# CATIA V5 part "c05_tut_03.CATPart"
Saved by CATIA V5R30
Part number: Part1
Bounding box of the stored display mesh (mm): x -75 to 75, y -150 to 150, z 39 to 189
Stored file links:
  D:\PROJECTS\CATIA V56R 2020\Resources\c05_catia_v5_6r2020_tut\c05_tut_03.CATPart
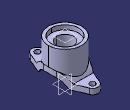
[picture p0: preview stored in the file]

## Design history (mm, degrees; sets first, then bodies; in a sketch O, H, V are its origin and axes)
Body1 (main body)
  Sketch1 on yz-plane, origin (0, 0, 0), H (0, 1, 0), V (0, 0, 1)
    arc A1 centre (0, 0) radius 105 from (83.2406, 64) to (-83.2406, 64) ccw
    arc A2 centre (0, 0) radius 80 from (69.8498, 39) to (-69.8498, 39) ccw
    line L1 (69.8498, 39) -> (150, 39)
    line L2 (150, 39) -> (150, 64)
    line L3 (150, 64) -> (83.2406, 64)
    point P5 (-83.2406, 64)
    line L4 (-83.2406, 64) -> (-150, 64)
    line L5 (-150, 64) -> (-150, 39)
    point P7 (-150, 39)
    line L6 (-150, 39) -> (-69.8498, 39)
    radius A1 = 105
    radius A2 = 80
    distance L3 L1 = 25
    distance H L1 = 39
    distance V L5 = 150
    horizontal: L1 H, L3 H, L4 H, L6 H
    vertical: L2 V, L5 V
    coincidence: P5 L3, P7 L1
    symmetry: L5 L2 V
  Pad1: profile Sketch1, direction (1, 0, 0), length 75, mirrored extent
  Sketch2 on xy-plane, origin (0, 0, 0), H (1, 0, 0), V (0, 1, 0)
    arc A1 centre (0, 0) radius 75 from (-68.7386, 30) to (-68.7386, -30) ccw
    arc A2 centre (0, 125) radius 25 from (22.9129, 135) to (-22.9129, 135) ccw
    point P1 (0, 125)
    point P2 (0, 150)
    arc A3 centre (0, -125) radius 25 from (-22.9129, -135) to (22.9129, -135) ccw
    point P3 (0, -125)
    reference projected line E1 (-75, 150) -> (75, 150) from edge [face of Pad1 from Sketch1.L3 | face of Pad1 from Sketch1.L2]
    reference projected line E2 (-75, -150) -> (75, -150) from edge [face of Pad1 from Sketch1.L5 | face of Pad1 from Sketch1.L4]
    reference projected line E3 (75, 83.2406) -> (75, -83.2406) from edge [face of Pad1 from Sketch1.A1 | end face of Pad1]
    line L1 (22.9129, 135) -> (68.7386, 30)
    line L2 (-22.9129, 135) -> (-68.7386, 30)
    line L3 (-22.9129, -135) -> (-68.7386, -30)
    line L4 (22.9129, -135) -> (68.7386, -30)
    point P11 (68.7386, -30)
    arc A4 centre (0, 0) radius 75 from (68.7386, -30) to (68.7386, 30) ccw
    radius A2 = 25
    coincidence: P1 V, A2 P2, P2 V, P3 V, A1 P11, A1 A4
    tangency: A2 E1, A3 E2, A1 E3, L1 A2, L1 A1, L2 A2, L2 A1, L3 A3, L3 A1, L4 A3, L4 A1
    symmetry: A2 A3 H
  Pocket1: profile Sketch2, direction (0, 0, 1), through (limit type 3), outer side
  Plane1: type Offset, RefPlane xy-plane, Offset 189
  Sketch3 on Plane1, origin (0, 0, 189), H (1, 0, 0), V (0, 1, 0)
    circle A1 centre (0, 0) radius 75
    reference projected arc E1 centre (0, 0) radius 75 from (68.7386, -30) to (68.7386, 30) ccw from edge [face of Pad1 from Sketch1.A1 | face of Pocket1]
    radius A1 = 75
    concentricity: A1 E1
  Pad2: profile Sketch3, direction (0, 0, 1), up to face of Pad1 from Sketch1.A1
  Sketch4 on yz-plane, origin (0, 0, 0), H (0, 1, 0), V (0, 0, 1)
    point P1 (0, 39)
    line L1 (0, 39) -> (0, 189)
    line L2 (0, 189) -> (61.5, 189)
    line L3 (61.5, 189) -> (61.5, 169)
    line L4 (61.5, 169) -> (37.5, 169)
    line L5 (37.5, 169) -> (37.5, 39)
    line L6 (37.5, 39) -> (0, 39)
    reference projected line E1 (-75, 189) -> (75, 189) from edge [face of Pad2 from Sketch3.A1 | start face of Pad2]
    axis line L7 (0, 189) -> (0, 254.467)
    reference projected line E2 (135, 39) -> (69.8498, 39) from edge [face of Pocket1 from Sketch2.L1 | face of Pad1 from Sketch1.L1]
    distance L2 L4 = 20
    radius about axis L5 L7 = 37.5
    radius about axis L7 L3 = 61.5
    coincidence: P1 V, L2 E1, L6 E2
    vertical: L1 V, L3 V, L5 V, L7 V
    horizontal: L2 H, L4 H, L6 H
  Groove1: profile Sketch4, axis Sketch4.L7, angle 360
  Sketch5 on face of Pad1 from Sketch1.L3, origin (0, 0, 64), H (1, 0, 0), V (0, 1, 0)
    circle A1 centre (0, 125) radius 12.5
    point P1 (0, 125)
    circle A2 centre (0, -125) radius 12.5
    point P2 (0, -125)
    reference projected arc E1 centre (0, 125) radius 25 from (22.9129, 135) to (-22.9129, 135) ccw from edge [face of Pocket1 | face of Pad1 from Sketch1.L3]
    reference projected arc E2 centre (0, -125) radius 25 from (-22.9129, -135) to (22.9129, -135) ccw from edge [face of Pocket1 | face of Pad1 from Sketch1.L4]
    radius A1 = 12.5
    coincidence: P1 V, P2 V
    concentricity: A1 E1, A2 E2
    equal size: A1 A2
  Pocket2: profile Sketch5, direction (0, 0, -1), through (limit type 3)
